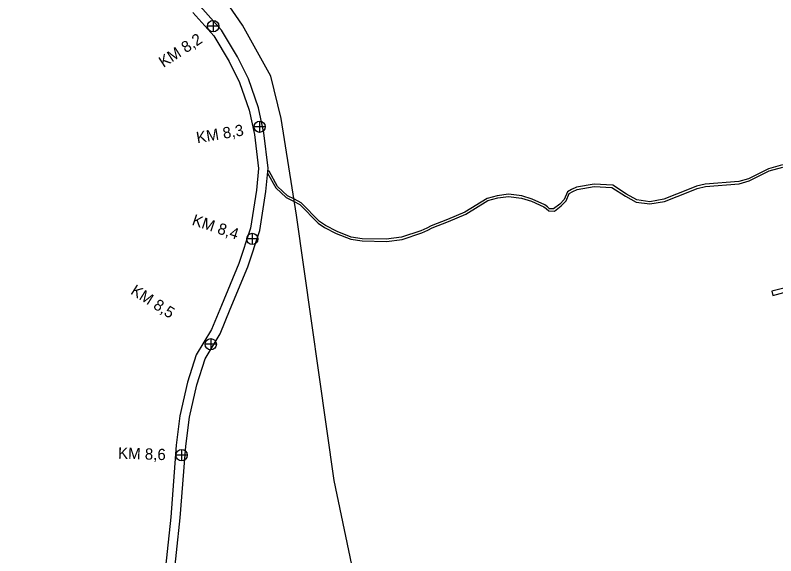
# Model space of a CAD drawing. Extents: x -478232 to -472707, y -1118753 to -1113967.
# Drawn here: x -476365 to -475690, y -1116794 to -1116314 of the extents above; entities that cross this region are included whole.
import ezdxf

# ---------------------------------------------------------------- set-up
doc = ezdxf.new("R2010")
doc.units = 0
for name, color, linetype in [('ObPÚ', 7, 'Continuous'), ('silnice', 7, 'Continuous'), ('staničení toku', 7, 'Continuous'), ('vodní plochy', 7, 'Continuous')]:
    doc.layers.add(name, color=color, linetype=linetype)

msp = doc.modelspace()

# ---------------------------------------------------------------- linework, layer by layer
at = {"layer": 'ObPÚ'}
msp.add_lwpolyline([(-475631.84, -1116543.64), (-475693.15, -1116558.84), (-475692.22, -1116562.71), (-475661.8, -1116554.61)], dxfattribs=at)
at = {"layer": 'silnice'}
msp.add_lwpolyline([(-475903.982, -1117378.322), (-475889.519, -1117318.176), (-475888.389, -1117289.008), (-475895.395, -1117261.196), (-475916.638, -1117209.19), (-475969.886, -1117075.455), (-476021.05, -1116948.737), (-476052.923, -1116863.979), (-476081.44, -1116727.192), (-476114.99, -1116491.378), (-476128.411, -1116405.781), (-476137.637, -1116368.017), (-476162.8, -1116322.7), (-476200.543, -1116268.153), (-476239.965, -1116179.199), (-476260.934, -1116109.546), (-476288.613, -1116007.164), (-476289.451, -1115970.24), (-476274.354, -1115930.798), (-476261.922, -1115907.288), (-476366.595, -1115823.727)], dxfattribs=at)
at = {"layer": 'staničení toku'}
for p, q in [((-476188.887, -1116318.693), (-476188.887, -1116328.693)), ((-476183.887, -1116323.693), (-476193.887, -1116323.693)), ((-476147.632, -1116408.003), (-476147.632, -1116418.003)), ((-476142.632, -1116413.003), (-476152.632, -1116413.003)), ((-476154.16, -1116507.558), (-476154.16, -1116517.558)), ((-476149.16, -1116512.558), (-476159.16, -1116512.558)), ((-476191.071, -1116601.059), (-476191.071, -1116611.059)), ((-476186.071, -1116606.059), (-476196.071, -1116606.059)), ((-476211.904, -1116704.598), (-476221.904, -1116704.598)), ((-476216.904, -1116699.598), (-476216.904, -1116709.598))]:
    msp.add_line(p, q, dxfattribs=at)
for centre in [(-476188.887, -1116323.693), (-476147.632, -1116413.003), (-476154.16, -1116512.558), (-476191.071, -1116606.059), (-476216.904, -1116704.598)]:
    msp.add_circle(centre, 5, dxfattribs=at)
at = {"layer": 'vodní plochy'}
for points in [[(-476224.65, -1116821.748), (-476218.166, -1116760.281), (-476213.201, -1116696.598), (-476209.998, -1116670.976), (-476203.505, -1116642.118), (-476196.126, -1116619.013), (-476182.743, -1116596.919), (-476173.799, -1116575.066), (-476158.205, -1116537.488), (-476147.489, -1116505.088), (-476142.144, -1116470.444), (-476140.228, -1116449.843), (-476143.996, -1116418.501), (-476148.705, -1116396.123), (-476157.644, -1116370.468), (-476167.296, -1116350.92), (-476181.445, -1116327.327), (-476200.558, -1116305.872)], [(-476206.824, -1116311.554), (-476188.29, -1116332.359), (-476174.728, -1116354.975), (-476165.46, -1116373.745), (-476156.871, -1116398.395), (-476152.35, -1116419.879), (-476148.734, -1116449.957), (-476150.542, -1116469.407), (-476155.741, -1116503.101), (-476166.138, -1116534.535), (-476181.62, -1116571.843), (-476190.32, -1116593.102), (-476203.88, -1116615.486), (-476211.676, -1116639.899), (-476218.341, -1116669.52), (-476221.619, -1116695.744), (-476226.591, -1116759.508), (-476233.031, -1116820.563)], [(-475683.608, -1116446.891), (-475696.084, -1116450.304), (-475713.807, -1116459.166), (-475722.473, -1116461.738), (-475752.339, -1116463.951), (-475759.965, -1116465.787), (-475766.557, -1116468.482), (-475788.947, -1116477.312), (-475801.381, -1116479.523), (-475812.887, -1116477.879), (-475821.999, -1116472.906), (-475834.317, -1116464.881), (-475850.769, -1116464.015), (-475866.412, -1116466.645), (-475870.757, -1116468.713), (-475874.45, -1116470.846), (-475877.363, -1116477.6), (-475881.336, -1116481.661), (-475886.708, -1116485.855), (-475890.269, -1116485.746), (-475892.098, -1116484.147), (-475894.417, -1116482.341), (-475905.696, -1116477.223), (-475914.798, -1116474.293), (-475926.788, -1116472.876), (-475936.751, -1116474.218), (-475945.782, -1116476.716), (-475965.569, -1116488.784), (-475980.889, -1116495.327), (-475995.516, -1116500.833), (-475999.401, -1116503.085), (-476004.548, -1116505.283), (-476021.706, -1116511.065), (-476035.253, -1116512.736), (-476056.535, -1116512.362), (-476066.322, -1116510.884), (-476078.941, -1116506.058), (-476089.177, -1116500.614), (-476094.447, -1116497.102), (-476110.893, -1116480.408), (-476116.755, -1116477.223), (-476122.949, -1116474.265), (-476131.753, -1116466.076), (-476139.274, -1116452.519), (-476140.406, -1116451.764)], [(-476021.26, -1116513.025), (-476003.834, -1116507.153), (-475998.503, -1116504.877), (-475994.656, -1116502.647), (-475980.143, -1116497.183), (-475964.651, -1116490.566), (-475944.98, -1116478.57), (-475936.349, -1116476.182), (-475926.772, -1116474.892), (-475915.226, -1116476.257), (-475906.418, -1116479.091), (-475895.459, -1116484.065), (-475893.372, -1116485.689), (-475891.047, -1116487.724), (-475886.046, -1116487.877), (-475880, -1116483.155), (-475875.673, -1116478.734), (-475872.876, -1116472.246), (-475869.825, -1116470.485), (-475865.804, -1116468.571), (-475850.655, -1116466.023), (-475834.959, -1116466.849), (-475823.025, -1116474.624), (-475813.527, -1116479.807), (-475801.347, -1116481.549), (-475788.399, -1116479.246), (-475765.811, -1116470.338), (-475759.349, -1116467.695), (-475752.029, -1116465.933), (-475722.111, -1116463.716), (-475713.069, -1116461.034), (-475695.366, -1116452.182), (-475683.312, -1116448.883)], [(-476140.406, -1116451.764), (-476140.632, -1116454.194)], [(-476140.632, -1116454.194), (-476133.347, -1116467.324), (-476124.087, -1116475.937), (-476117.665, -1116479.005), (-476112.109, -1116482.024), (-476095.727, -1116498.652), (-476090.203, -1116502.334), (-476079.771, -1116507.882), (-476066.834, -1116512.83), (-476056.703, -1116514.36), (-476035.147, -1116514.738), (-476021.26, -1116513.025)]]:
    msp.add_lwpolyline(points, dxfattribs=at)

# ---------------------------------------------------------------- texts
at = {"layer": 'staničení toku'}
for s, rotation, p in [('KM 8,2', 32.985937, (-476233.061, -1116360.799)), ('KM 8,3', 9.563856, (-476203.002, -1116427.653)), ('KM 8,4', 341.522575, (-476208.422, -1116499.941)), ('KM 8,5', 327.636986, (-476262.92, -1116560.953)), ('KM 8,6', 358.042465, (-476273.456, -1116707.603))]:
    msp.add_text(s, height=10, rotation=rotation, dxfattribs=at).set_placement(p)

doc.saveas('drawing.dxf')
